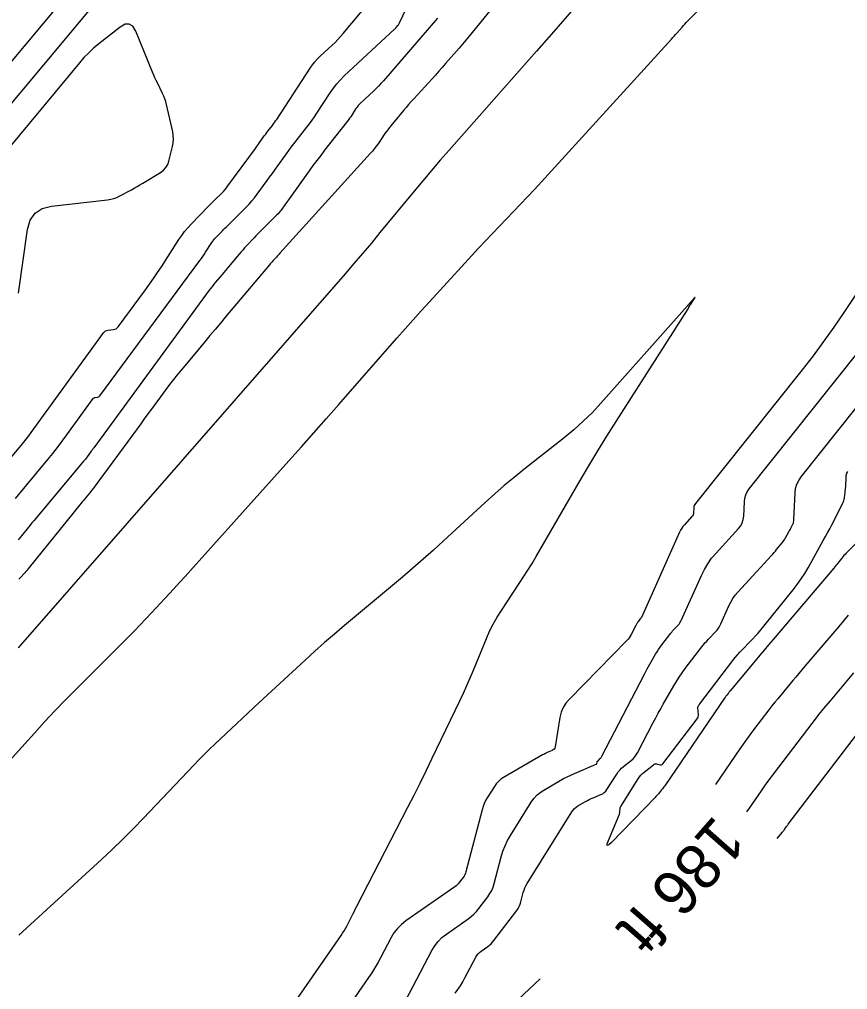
# Model space of a CAD drawing. Extents: x 7585033 to 7595090, y 547091 to 553471.
# Drawn here: x 7586662.6 to 7586777.6, y 547449.5 to 547584.2 of the extents above; entities that cross this region are included whole.
import ezdxf

# ---------------------------------------------------------------- set-up
doc = ezdxf.new("R2010")
doc.units = 0
for name, color, linetype in [('E_TERR_DSPLAY_GeneralTx', 7, 'Continuous'), ('E_TERR_DSPLAY_MajContour', 7, 'Continuous'), ('E_TERR_DSPLAY_MinContour', 7, 'Continuous')]:
    doc.layers.add(name, color=color, linetype=linetype)

msp = doc.modelspace()

# ---------------------------------------------------------------- linework, layer by layer
at = {"layer": 'E_TERR_DSPLAY_MajContour'}
for points in [[(7586675.33, 547589.16), (7586659.82, 547570.53)], [(7586661.39, 547523.25), (7586662.85, 547525.02), (7586663.21, 547525.46), (7586663.56, 547525.91), (7586663.91, 547526.37), (7586664.25, 547526.83), (7586674.3, 547540.67), (7586674.42, 547540.81), (7586674.57, 547540.92), (7586674.73, 547540.99), (7586674.92, 547541.03), (7586675.69, 547541.12), (7586675.88, 547541.16), (7586676.04, 547541.23), (7586676.19, 547541.34), (7586676.32, 547541.48), (7586680.11, 547546.62), (7586680.68, 547547.4), (7586681.24, 547548.2), (7586681.79, 547549.01), (7586682.33, 547549.83), (7586684.75, 547553.59), (7586685.14, 547554.16), (7586685.55, 547554.7), (7586685.99, 547555.23), (7586686.46, 547555.73), (7586688.88, 547558.22), (7586689.11, 547558.45), (7586689.34, 547558.69), (7586689.57, 547558.92), (7586689.8, 547559.15), (7586690.72, 547560.06), (7586690.95, 547560.29), (7586691.16, 547560.53), (7586691.37, 547560.78), (7586691.56, 547561.04), (7586695.36, 547566.26), (7586695.5, 547566.46), (7586695.65, 547566.65), (7586695.79, 547566.85), (7586695.93, 547567.05), (7586696.51, 547567.85), (7586696.65, 547568.05), (7586696.8, 547568.25), (7586696.94, 547568.44), (7586697.09, 547568.64), (7586697.73, 547569.45), (7586697.89, 547569.65), (7586698.04, 547569.86), (7586698.18, 547570.07), (7586698.33, 547570.28), (7586702.96, 547577.37), (7586703.28, 547577.83), (7586703.62, 547578.27), (7586703.99, 547578.68), (7586704.38, 547579.07), (7586706.01, 547580.59), (7586706.42, 547580.97), (7586706.8, 547581.37), (7586707.18, 547581.78), (7586707.54, 547582.2), (7586712.13, 547587.7)], [(7586739.21, 547585.27), (7586736.8, 547582.49), (7586734.38, 547579.73), (7586722.26, 547566.02), (7586721.03, 547564.62), (7586719.81, 547563.2), (7586718.6, 547561.77), (7586717.41, 547560.33), (7586712.66, 547554.56), (7586711.47, 547553.12), (7586710.27, 547551.69), (7586709.05, 547550.27), (7586707.83, 547548.85), (7586662.43, 547496.92)], [(7586714.67, 547445.04), (7586719.85, 547454.92), (7586720.25, 547455.58), (7586720.72, 547456.19), (7586721.26, 547456.73), (7586721.88, 547457.21), (7586724.91, 547459.33), (7586725.32, 547459.64), (7586725.7, 547459.98), (7586726.05, 547460.35), (7586726.38, 547460.74), (7586727.63, 547462.39), (7586727.92, 547462.82), (7586728.16, 547463.26), (7586728.36, 547463.73), (7586728.51, 547464.22), (7586729.48, 547467.93), (7586729.72, 547468.7), (7586730.01, 547469.45), (7586730.35, 547470.17), (7586730.75, 547470.87), (7586733.66, 547475.53), (7586734.01, 547476.03), (7586734.42, 547476.47), (7586734.88, 547476.87), (7586735.39, 547477.2), (7586737.65, 547478.51), (7586738.14, 547478.78), (7586738.63, 547479.04), (7586739.14, 547479.28), (7586739.65, 547479.5), (7586742.67, 547480.77), (7586742.71, 547480.79), (7586742.73, 547480.81), (7586742.75, 547480.85), (7586742.76, 547480.89), (7586742.79, 547481.06), (7586742.8, 547481.1), (7586742.82, 547481.14), (7586742.84, 547481.18), (7586742.87, 547481.21), (7586743.22, 547481.57), (7586743.29, 547481.64), (7586743.35, 547481.72), (7586743.4, 547481.8), (7586743.45, 547481.89), (7586749.38, 547493.3), (7586749.57, 547493.65), (7586749.75, 547494), (7586749.94, 547494.34), (7586750.13, 547494.68), (7586750.91, 547496.05), (7586751.11, 547496.39), (7586751.32, 547496.72), (7586751.55, 547497.04), (7586751.78, 547497.36), (7586753.02, 547498.99), (7586753.14, 547499.13), (7586753.26, 547499.28), (7586753.39, 547499.42), (7586753.52, 547499.56), (7586754.04, 547500.1), (7586754.17, 547500.24), (7586754.28, 547500.39), (7586754.38, 547500.55), (7586754.46, 547500.71), (7586757.26, 547506.98), (7586757.68, 547507.81), (7586758.15, 547508.61), (7586758.69, 547509.36), (7586759.3, 547510.07), (7586762.43, 547513.48), (7586762.72, 547513.87), (7586762.94, 547514.28), (7586763.08, 547514.73), (7586763.14, 547515.21), (7586763.23, 547517.2), (7586763.29, 547517.69), (7586763.42, 547518.15), (7586763.62, 547518.58), (7586763.9, 547518.98), (7586785.06, 547545.5)], [(7586778.39, 547493.45), (7586776.05, 547490.68), (7586775.81, 547490.41), (7586775.58, 547490.14), (7586775.35, 547489.86), (7586775.13, 547489.59), (7586774.21, 547488.49), (7586773.98, 547488.22), (7586773.76, 547487.94), (7586773.54, 547487.66), (7586773.32, 547487.38), (7586767.22, 547479.4), (7586766.79, 547478.83), (7586766.36, 547478.25), (7586765.94, 547477.66), (7586765.54, 547477.07), (7586763.91, 547474.7), (7586763.53, 547474.16)]]:
    msp.add_lwpolyline(points, dxfattribs=at)
at = {"layer": 'E_TERR_DSPLAY_MinContour'}
for points in [[(7586742.56, 547603.37), (7586725.47, 547582.36), (7586725.02, 547581.81), (7586724.57, 547581.26), (7586724.11, 547580.72), (7586723.64, 547580.18), (7586721.77, 547578.04), (7586721.31, 547577.5), (7586720.83, 547576.97), (7586720.36, 547576.44), (7586719.88, 547575.91), (7586717.36, 547573.15), (7586716.99, 547572.75), (7586716.63, 547572.34), (7586716.28, 547571.93), (7586715.93, 547571.51), (7586714.38, 547569.66), (7586714.11, 547569.33), (7586713.85, 547568.99), (7586713.6, 547568.65), (7586713.35, 547568.3), (7586712.39, 547566.9), (7586712.14, 547566.56), (7586711.88, 547566.22), (7586711.61, 547565.89), (7586711.33, 547565.57), (7586698.78, 547551.71), (7586698.66, 547551.57), (7586698.54, 547551.44), (7586698.41, 547551.31), (7586698.29, 547551.17), (7586697.8, 547550.64), (7586697.68, 547550.51), (7586697.56, 547550.38), (7586697.44, 547550.24), (7586697.32, 547550.1), (7586691.24, 547542.88), (7586690.51, 547542.01), (7586689.78, 547541.14), (7586689.06, 547540.27), (7586688.33, 547539.4), (7586685.05, 547535.48), (7586684.51, 547534.82), (7586683.98, 547534.16), (7586683.47, 547533.49), (7586682.96, 547532.81), (7586680.95, 547530.08), (7586680.45, 547529.39), (7586679.95, 547528.71), (7586679.45, 547528.03), (7586678.95, 547527.34), (7586673.01, 547519.25), (7586672.85, 547519.03), (7586672.68, 547518.82), (7586672.52, 547518.61), (7586672.35, 547518.41), (7586671.66, 547517.59), (7586671.49, 547517.38), (7586671.32, 547517.18), (7586671.15, 547516.97), (7586670.98, 547516.76), (7586663.99, 547508.09), (7586663.83, 547507.9), (7586663.68, 547507.72), (7586663.52, 547507.54), (7586663.36, 547507.36), (7586662.7, 547506.66), (7586662.54, 547506.48)], [(7586668.71, 547586.99), (7586660.44, 547577.05)], [(7586662.07, 547517.64), (7586666.56, 547523.09), (7586667.24, 547523.92), (7586667.9, 547524.76), (7586668.55, 547525.61), (7586669.19, 547526.48), (7586672.86, 547531.54), (7586672.92, 547531.6), (7586672.98, 547531.65), (7586673.06, 547531.69), (7586673.15, 547531.7), (7586673.5, 547531.74), (7586673.59, 547531.76), (7586673.67, 547531.8), (7586673.73, 547531.85), (7586673.79, 547531.91), (7586687.67, 547550.7), (7586687.88, 547550.98), (7586688.08, 547551.27), (7586688.27, 547551.55), (7586688.46, 547551.84), (7586689.32, 547553.18), (7586689.46, 547553.38), (7586689.6, 547553.57), (7586689.76, 547553.76), (7586689.93, 547553.94), (7586690.61, 547554.64), (7586690.78, 547554.81), (7586690.95, 547554.99), (7586691.12, 547555.16), (7586691.29, 547555.33), (7586694.09, 547558.11), (7586694.5, 547558.53), (7586694.89, 547558.96), (7586695.26, 547559.41), (7586695.61, 547559.88), (7586697.01, 547561.79), (7586697.34, 547562.25), (7586697.68, 547562.71), (7586698.01, 547563.18), (7586698.34, 547563.64), (7586699.67, 547565.49), (7586700, 547565.96), (7586700.34, 547566.41), (7586700.69, 547566.87), (7586701.04, 547567.32), (7586702.52, 547569.21), (7586702.88, 547569.68), (7586703.23, 547570.16), (7586703.57, 547570.64), (7586703.9, 547571.13), (7586705.76, 547573.98), (7586706.19, 547574.61), (7586706.67, 547575.2), (7586707.17, 547575.77), (7586707.71, 547576.31), (7586714.66, 547582.78), (7586714.73, 547582.84), (7586714.79, 547582.91), (7586714.86, 547582.98), (7586714.92, 547583.05), (7586715.18, 547583.35), (7586715.24, 547583.42), (7586715.29, 547583.5), (7586715.34, 547583.58), (7586715.39, 547583.67), (7586716.81, 547586.68)], [(7586658.1, 547477.81), (7586664.69, 547485.11), (7586666.11, 547486.65), (7586667.55, 547488.18), (7586669, 547489.7), (7586670.48, 547491.19), (7586677.77, 547498.48), (7586678.58, 547499.29), (7586679.37, 547500.11), (7586680.16, 547500.94), (7586680.95, 547501.78), (7586684.06, 547505.14), (7586684.83, 547505.99), (7586685.61, 547506.83), (7586686.38, 547507.68), (7586687.14, 547508.53), (7586700.01, 547522.9), (7586701.75, 547524.84), (7586703.48, 547526.79), (7586705.21, 547528.74), (7586706.93, 547530.7), (7586715.02, 547539.93), (7586716.14, 547541.2), (7586717.26, 547542.45), (7586718.38, 547543.71), (7586719.52, 547544.95), (7586724.44, 547550.33), (7586725.39, 547551.37), (7586726.35, 547552.4), (7586727.31, 547553.43), (7586728.28, 547554.45), (7586732.18, 547558.52), (7586733.15, 547559.54), (7586734.11, 547560.57), (7586735.07, 547561.6), (7586736.02, 547562.64), (7586753.12, 547581.42), (7586753.3, 547581.63), (7586753.49, 547581.83), (7586753.67, 547582.04), (7586753.86, 547582.25), (7586754.59, 547583.09), (7586754.77, 547583.3), (7586754.96, 547583.5), (7586755.15, 547583.71), (7586755.35, 547583.91), (7586757.76, 547586.34)], [(7586720.66, 547584.32), (7586713.13, 547575.63), (7586712.8, 547575.26), (7586712.47, 547574.91), (7586712.12, 547574.56), (7586711.77, 547574.22), (7586710.01, 547572.58), (7586709.82, 547572.4), (7586709.65, 547572.2), (7586709.48, 547571.99), (7586709.33, 547571.77), (7586708.75, 547570.88), (7586708.6, 547570.65), (7586708.44, 547570.44), (7586708.29, 547570.22), (7586708.12, 547570.01), (7586704.98, 547566), (7586704.43, 547565.29), (7586703.89, 547564.58), (7586703.36, 547563.86), (7586702.83, 547563.14), (7586699.96, 547559.13), (7586699.83, 547558.95), (7586699.71, 547558.77), (7586699.58, 547558.59), (7586699.45, 547558.42), (7586698.93, 547557.7), (7586698.79, 547557.53), (7586698.65, 547557.36), (7586698.51, 547557.19), (7586698.35, 547557.03), (7586696.26, 547554.96), (7586695.99, 547554.69), (7586695.72, 547554.41), (7586695.45, 547554.13), (7586695.19, 547553.85), (7586694.13, 547552.72), (7586693.87, 547552.44), (7586693.62, 547552.15), (7586693.36, 547551.86), (7586693.11, 547551.56), (7586691.65, 547549.83), (7586691.42, 547549.56), (7586691.2, 547549.29), (7586690.97, 547549.02), (7586690.74, 547548.75), (7586689.84, 547547.67), (7586689.62, 547547.39), (7586689.4, 547547.12), (7586689.18, 547546.84), (7586688.97, 547546.56), (7586672.94, 547524.71), (7586672.82, 547524.55), (7586672.71, 547524.39), (7586672.59, 547524.23), (7586672.47, 547524.07), (7586672.01, 547523.44), (7586671.89, 547523.28), (7586671.77, 547523.12), (7586671.64, 547522.97), (7586671.52, 547522.82), (7586664.84, 547514.85), (7586664.6, 547514.56), (7586664.36, 547514.27), (7586664.12, 547513.98), (7586663.88, 547513.68), (7586662.93, 547512.5), (7586662.69, 547512.21), (7586662.44, 547511.92)], [(7586662.47, 547546.16), (7586663.75, 547555.02), (7586664.12, 547556.31), (7586664.79, 547557.27), (7586665.78, 547557.91), (7586667.07, 547558.24), (7586674.86, 547559.12), (7586675.31, 547559.19), (7586675.74, 547559.3), (7586676.16, 547559.46), (7586676.56, 547559.65), (7586678.16, 547560.52), (7586678.56, 547560.74), (7586678.96, 547560.96), (7586679.35, 547561.19), (7586679.74, 547561.43), (7586682.21, 547562.92), (7586682.62, 547563.22), (7586682.95, 547563.58), (7586683.2, 547564), (7586683.36, 547564.48), (7586683.87, 547566.52), (7586683.96, 547567.03), (7586684, 547567.54), (7586683.97, 547568.05), (7586683.89, 547568.56), (7586683.03, 547572.36), (7586682.92, 547572.75), (7586682.8, 547573.14), (7586682.65, 547573.51), (7586682.48, 547573.88), (7586681.76, 547575.34), (7586681.58, 547575.7), (7586681.41, 547576.07), (7586681.25, 547576.44), (7586681.09, 547576.82), (7586678.77, 547582.51), (7586678.37, 547583.2), (7586677.87, 547583.52), (7586677.28, 547583.48), (7586676.59, 547583.08), (7586673.64, 547580.75), (7586672.92, 547580.15), (7586672.24, 547579.52), (7586671.58, 547578.85), (7586670.97, 547578.14), (7586659.2, 547564.01)], [(7586784.99, 547555.41), (7586777.04, 547543.47), (7586775.66, 547541.43), (7586774.23, 547539.43), (7586772.76, 547537.46), (7586771.25, 547535.53), (7586756.43, 547516.96), (7586756.34, 547516.83), (7586756.27, 547516.68), (7586756.23, 547516.53), (7586756.21, 547516.37), (7586756.18, 547515.72), (7586756.16, 547515.56), (7586756.12, 547515.41), (7586756.04, 547515.27), (7586755.95, 547515.15), (7586754.91, 547514.02), (7586754.71, 547513.79), (7586754.54, 547513.54), (7586754.38, 547513.28), (7586754.24, 547513), (7586748.94, 547501.15), (7586748.93, 547501.12), (7586748.91, 547501.1), (7586748.89, 547501.08), (7586748.88, 547501.06), (7586748.8, 547500.98), (7586748.78, 547500.95), (7586748.76, 547500.93), (7586748.74, 547500.91), (7586748.72, 547500.89), (7586748.54, 547500.65), (7586748.5, 547500.6), (7586748.47, 547500.55), (7586748.44, 547500.5), (7586748.41, 547500.45), (7586748.29, 547500.25), (7586748.26, 547500.2), (7586748.23, 547500.14), (7586748.21, 547500.09), (7586748.18, 547500.04), (7586747.52, 547498.77), (7586747.39, 547498.54), (7586747.25, 547498.33), (7586747.09, 547498.13), (7586746.92, 547497.94), (7586738.94, 547489.83), (7586738.47, 547489.27), (7586738.09, 547488.66), (7586737.81, 547487.99), (7586737.64, 547487.27), (7586736.95, 547483.18), (7586736.91, 547483.01), (7586736.82, 547482.87), (7586736.71, 547482.76), (7586736.55, 547482.68), (7586735.88, 547482.39), (7586735.71, 547482.32), (7586735.54, 547482.24), (7586735.38, 547482.15), (7586735.22, 547482.06), (7586729.81, 547478.94), (7586729.43, 547478.69), (7586729.09, 547478.4), (7586728.79, 547478.07), (7586728.53, 547477.7), (7586727.55, 547476.13), (7586727.32, 547475.74), (7586727.13, 547475.32), (7586726.96, 547474.9), (7586726.83, 547474.46), (7586724.58, 547465.85), (7586724.51, 547465.64), (7586724.42, 547465.44), (7586724.32, 547465.25), (7586724.2, 547465.07), (7586723.66, 547464.36), (7586723.52, 547464.19), (7586723.37, 547464.04), (7586723.21, 547463.89), (7586723.03, 547463.76), (7586716.24, 547459.03), (7586715.63, 547458.54), (7586715.08, 547457.99), (7586714.6, 547457.38), (7586714.2, 547456.71), (7586712.72, 547453.89), (7586712.34, 547453.19), (7586711.94, 547452.5), (7586711.52, 547451.83), (7586711.08, 547451.17), (7586707.78, 547446.41)], [(7586699.71, 547446.12), (7586707.25, 547456.99), (7586707.46, 547457.31), (7586707.67, 547457.64), (7586707.86, 547457.98), (7586708.04, 547458.32), (7586708.75, 547459.7), (7586708.93, 547460.04), (7586709.11, 547460.38), (7586709.28, 547460.73), (7586709.46, 547461.07), (7586716.52, 547474.81), (7586717.38, 547476.48), (7586718.22, 547478.16), (7586719.05, 547479.84), (7586719.87, 547481.53), (7586723.74, 547489.58), (7586724.24, 547490.64), (7586724.72, 547491.69), (7586725.18, 547492.76), (7586725.63, 547493.83), (7586727.43, 547498.22), (7586727.88, 547499.24), (7586728.37, 547500.23), (7586728.92, 547501.19), (7586729.51, 547502.13), (7586731.98, 547505.84), (7586732.59, 547506.77), (7586733.19, 547507.71), (7586733.77, 547508.66), (7586734.33, 547509.62), (7586740.44, 547520.14), (7586741.66, 547522.2), (7586742.9, 547524.26), (7586744.15, 547526.3), (7586745.43, 547528.33), (7586755.41, 547543.99), (7586755.44, 547544.05), (7586755.48, 547544.1), (7586755.51, 547544.16), (7586755.54, 547544.21), (7586755.66, 547544.43), (7586755.69, 547544.49), (7586755.73, 547544.54), (7586755.76, 547544.59), (7586755.79, 547544.65), (7586756.3, 547545.42), (7586756.36, 547545.53), (7586756.38, 547545.57), (7586756.34, 547545.55), (7586756.26, 547545.46), (7586755.65, 547544.78), (7586755.62, 547544.74), (7586755.59, 547544.71), (7586755.55, 547544.67), (7586755.52, 547544.64), (7586755.4, 547544.5), (7586755.36, 547544.47), (7586755.33, 547544.43), (7586755.3, 547544.4), (7586755.27, 547544.36), (7586743.33, 547530.91), (7586742.13, 547529.62), (7586740.88, 547528.38), (7586739.57, 547527.2), (7586738.2, 547526.08), (7586732.64, 547521.7), (7586731.26, 547520.59), (7586729.91, 547519.46), (7586728.58, 547518.3), (7586727.27, 547517.11), (7586721.49, 547511.77), (7586720.09, 547510.49), (7586718.67, 547509.22), (7586717.24, 547507.98), (7586715.79, 547506.75), (7586707.73, 547500.02), (7586706.34, 547498.85), (7586704.98, 547497.66), (7586703.63, 547496.46), (7586702.29, 547495.24), (7586695.85, 547489.29), (7586695.09, 547488.59), (7586694.32, 547487.88), (7586693.56, 547487.16), (7586692.8, 547486.45), (7586689.77, 547483.59), (7586689.01, 547482.87), (7586688.27, 547482.14), (7586687.54, 547481.4), (7586686.82, 547480.64), (7586679.83, 547473.27), (7586678.42, 547471.8), (7586676.97, 547470.36), (7586675.51, 547468.95), (7586674.02, 547467.56), (7586662.52, 547457.03)], [(7586723.11, 547448.98), (7586723.48, 547449.5), (7586723.82, 547450.03), (7586724.15, 547450.58), (7586724.45, 547451.13), (7586725.96, 547454), (7586726.1, 547454.24), (7586726.28, 547454.46), (7586726.47, 547454.66), (7586726.7, 547454.84), (7586727.64, 547455.5), (7586727.87, 547455.67), (7586728.09, 547455.86), (7586728.28, 547456.07), (7586728.47, 547456.29), (7586731.63, 547460.47), (7586731.82, 547460.75), (7586731.98, 547461.04), (7586732.11, 547461.35), (7586732.21, 547461.67), (7586732.55, 547462.98), (7586732.65, 547463.31), (7586732.77, 547463.62), (7586732.91, 547463.92), (7586733.08, 547464.21), (7586739.3, 547474.17), (7586739.47, 547474.41), (7586739.67, 547474.63), (7586739.89, 547474.82), (7586740.14, 547474.98), (7586741.19, 547475.59), (7586741.45, 547475.74), (7586741.71, 547475.87), (7586741.97, 547476), (7586742.24, 547476.11), (7586743.31, 547476.56), (7586743.57, 547476.69), (7586743.79, 547476.86), (7586743.99, 547477.05), (7586744.16, 547477.28), (7586745.51, 547479.41), (7586745.71, 547479.7), (7586745.93, 547479.97), (7586746.17, 547480.21), (7586746.44, 547480.44), (7586747.54, 547481.31), (7586747.8, 547481.54), (7586748.03, 547481.8), (7586748.23, 547482.07), (7586748.41, 547482.37), (7586750.59, 547486.56), (7586750.92, 547487.21), (7586751.27, 547487.85), (7586751.62, 547488.48), (7586751.98, 547489.12), (7586753.42, 547491.65), (7586753.79, 547492.27), (7586754.18, 547492.88), (7586754.59, 547493.48), (7586755.02, 547494.07), (7586757.32, 547497.08), (7586757.54, 547497.35), (7586757.76, 547497.62), (7586758, 547497.88), (7586758.24, 547498.14), (7586759.21, 547499.14), (7586759.44, 547499.4), (7586759.65, 547499.68), (7586759.83, 547499.97), (7586759.98, 547500.28), (7586761.09, 547502.77), (7586761.35, 547503.28), (7586761.64, 547503.76), (7586761.97, 547504.22), (7586762.33, 547504.65), (7586767.01, 547509.75), (7586767.19, 547509.95), (7586767.37, 547510.15), (7586767.54, 547510.36), (7586767.71, 547510.57), (7586768.47, 547511.5), (7586768.6, 547511.67), (7586768.72, 547511.84), (7586768.83, 547512.01), (7586768.93, 547512.19), (7586769.41, 547513.03), (7586769.47, 547513.16), (7586769.54, 547513.28), (7586769.61, 547513.4), (7586769.67, 547513.53), (7586770.01, 547514.2), (7586770.03, 547514.24), (7586770.05, 547514.28), (7586770.06, 547514.32), (7586770.07, 547514.36), (7586770.09, 547514.54), (7586770.1, 547514.58), (7586770.1, 547514.62), (7586770.1, 547514.67), (7586770.11, 547514.71), (7586770.27, 547518.43), (7586770.34, 547519.05), (7586770.51, 547519.63), (7586770.77, 547520.18), (7586771.12, 547520.69), (7586783.85, 547536.64)], [(7586779.96, 547512.62), (7586777.35, 547510.05), (7586777.2, 547509.89), (7586777.05, 547509.73), (7586776.9, 547509.56), (7586776.76, 547509.39), (7586776.21, 547508.69), (7586776.07, 547508.51), (7586775.93, 547508.34), (7586775.79, 547508.17), (7586775.65, 547508), (7586767.22, 547498.07), (7586766.6, 547497.35), (7586765.99, 547496.62), (7586765.38, 547495.9), (7586764.77, 547495.17), (7586761.24, 547490.95), (7586761.18, 547490.88), (7586761.13, 547490.81), (7586761.07, 547490.73), (7586761.01, 547490.66), (7586760.79, 547490.37), (7586760.73, 547490.3), (7586760.68, 547490.22), (7586760.63, 547490.15), (7586760.57, 547490.07), (7586752.17, 547477.78), (7586752.07, 547477.64), (7586751.97, 547477.5), (7586751.86, 547477.36), (7586751.75, 547477.23), (7586751.31, 547476.69), (7586751.2, 547476.56), (7586751.08, 547476.43), (7586750.96, 547476.3), (7586750.85, 547476.18), (7586744.8, 547469.92), (7586744.41, 547469.57), (7586744.21, 547469.5), (7586744.2, 547469.71), (7586744.37, 547470.2), (7586745.89, 547473.85), (7586745.92, 547473.93), (7586745.94, 547474.02), (7586745.96, 547474.11), (7586745.96, 547474.2), (7586745.97, 547474.57), (7586745.98, 547474.66), (7586746, 547474.75), (7586746.03, 547474.83), (7586746.07, 547474.91), (7586748.5, 547478.76), (7586748.68, 547479.02), (7586748.88, 547479.26), (7586749.1, 547479.48), (7586749.33, 547479.69), (7586750.62, 547480.71), (7586750.72, 547480.77), (7586750.82, 547480.81), (7586750.94, 547480.82), (7586751.05, 547480.81), (7586751.53, 547480.7), (7586751.64, 547480.69), (7586751.74, 547480.71), (7586751.84, 547480.76), (7586751.92, 547480.84), (7586756.68, 547487.08), (7586756.77, 547487.22), (7586756.83, 547487.37), (7586756.86, 547487.52), (7586756.85, 547487.69), (7586756.76, 547488.59), (7586756.76, 547488.64), (7586756.77, 547488.69), (7586756.78, 547488.75), (7586756.81, 547488.8), (7586756.92, 547488.99), (7586756.95, 547489.04), (7586756.98, 547489.09), (7586757.01, 547489.13), (7586757.04, 547489.18), (7586761.62, 547495.18), (7586761.94, 547495.58), (7586762.27, 547495.97), (7586762.6, 547496.35), (7586762.95, 547496.72), (7586765.08, 547498.91), (7586765.09, 547498.92), (7586765.09, 547498.92), (7586765.09, 547498.93), (7586765.09, 547498.93), (7586765.1, 547498.94), (7586765.12, 547498.96), (7586765.12, 547498.97), (7586765.13, 547498.97), (7586770, 547505), (7586770.57, 547505.73), (7586771.1, 547506.49), (7586771.6, 547507.26), (7586772.07, 547508.06), (7586774.18, 547511.82), (7586774.48, 547512.37), (7586774.77, 547512.91), (7586775.07, 547513.46), (7586775.35, 547514.02), (7586776.88, 547517), (7586776.96, 547517.17), (7586777.03, 547517.35), (7586777.08, 547517.54), (7586777.11, 547517.73), (7586777.22, 547518.51), (7586777.24, 547518.7), (7586777.26, 547518.89), (7586777.28, 547519.09), (7586777.29, 547519.28), (7586777.35, 547520.62), (7586777.38, 547520.9), (7586777.46, 547521.16), (7586777.58, 547521.41)], [(7586777.62, 547501.46), (7586776.98, 547500.68), (7586776.33, 547499.9), (7586771.63, 547494.38), (7586771.21, 547493.88), (7586770.79, 547493.38), (7586770.37, 547492.88), (7586769.95, 547492.38), (7586768.27, 547490.38), (7586767.86, 547489.87), (7586767.45, 547489.37), (7586767.04, 547488.86), (7586766.64, 547488.34), (7586764.49, 547485.53), (7586764.01, 547484.88), (7586763.53, 547484.23), (7586763.06, 547483.57), (7586762.6, 547482.91), (7586759.21, 547477.95)], [(7586767.77, 547470.45), (7586768.52, 547471.35), (7586768.59, 547471.44), (7586768.66, 547471.53), (7586768.73, 547471.62), (7586768.79, 547471.71), (7586769.05, 547472.09), (7586769.12, 547472.18), (7586769.18, 547472.28), (7586769.25, 547472.37), (7586769.32, 547472.46), (7586779.99, 547486.42)], [(7586734.87, 547451), (7586729.56, 547445.98)]]:
    msp.add_lwpolyline(points, dxfattribs=at)

# ---------------------------------------------------------------- texts
at = {"layer": 'E_TERR_DSPLAY_GeneralTx'}
msp.add_text('186 ft', height=6.3, rotation=228.7765, dxfattribs=at).set_placement((7586759.11, 547473.9))

doc.saveas('drawing.dxf')
